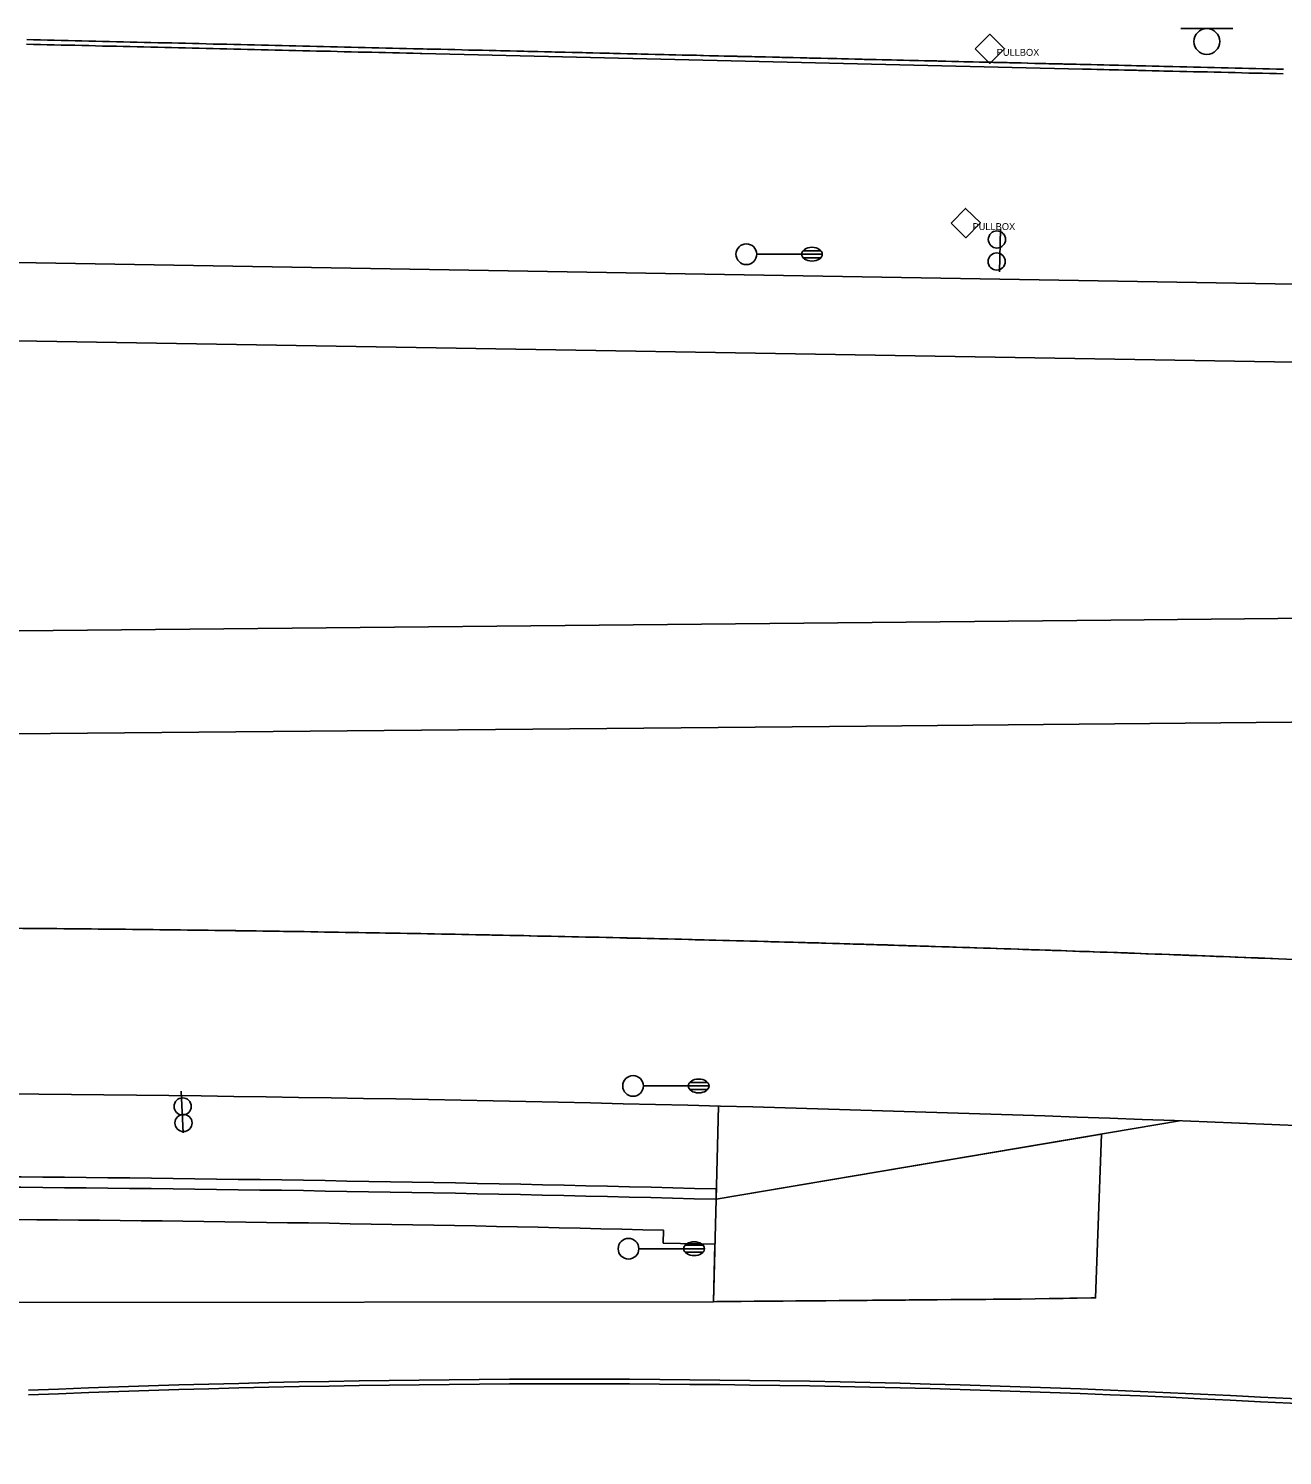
# Model space of a CAD drawing. Extents: x 2145380 to 2157287, y 139568 to 149130.
# Drawn here: x 2148110.3 to 2148291.9, y 142955.4 to 143162 of the extents above; entities that cross this region are included whole.
import ezdxf

# ---------------------------------------------------------------- set-up
doc = ezdxf.new("R2010")
doc.units = 0
for name, color, linetype in [('Default', 7, 'Continuous'), ('PR_PREVIOUSLY CONSTRUCTED', 7, 'Continuous'), ('TOPO_Asphalt', 7, 'Continuous'), ('TOPO_Curb Back', 7, 'Continuous'), ('TOPO_Light Pole', 7, 'Continuous'), ('TOPO_Misc', 7, 'Continuous'), ('TOPO_Power Pullbox', 7, 'Continuous'), ('TOPO_Sign', 7, 'Continuous')]:
    doc.layers.add(name, color=color, linetype=linetype)

# ---------------------------------------------------------------- blocks, each defined once
blk = doc.blocks.new('POST')
at = {"layer": 'TOPO_Misc'}
for start, end in [(90, 180), (180, 270), (360, 90), (270, 0)]:
    blk.add_arc((-0.01, 0.03), 3.16, start, end, dxfattribs=at)
blk = doc.blocks.new('LP')
at = {"layer": 'TOPO_Light Pole'}
blk.add_line((3.81, 0), (20.32, 0), dxfattribs=at)
for points in [[(20.32, 0), (27.94, 0)], [(20.32, 0), (23.5, 0)], [(20.83, 1.27), (27.43, 1.27)], [(20.83, 1.27), (23.5, 1.27)], [(23.71, 1.27), (27.43, 1.27)], [(23.71, 0), (27.94, 0)], [(20.83, -1.27), (27.43, -1.27)], [(20.83, -1.27), (23.5, -1.27)], [(23.71, -1.27), (27.43, -1.27)]]:
    blk.add_lwpolyline(points, dxfattribs=at)
blk.add_circle((0, 0), 3.81, dxfattribs=at)
blk.add_ellipse((24.13, 0), major_axis=(3.81, 0), ratio=0.666667, dxfattribs=at)
blk = doc.blocks.new('pulbox')
at = {"layer": 'Default'}
blk.add_lwpolyline([(-5.38, -0.01), (-0.02, 5.42), (5.4, 0.06), (0.05, -5.36), (-5.38, -0.01)], dxfattribs=at)
blk.add_text('PULLBOX', height=2.54, dxfattribs=at).set_placement((2.54, -2.54))

msp = doc.modelspace()

# ---------------------------------------------------------------- linework, layer by layer
at = {"layer": 'PR_PREVIOUSLY CONSTRUCTED'}
for p in [(2148210.23, 143005.99), (2148209.92, 142993.99)]:
    msp.add_line(p, (2148209.88, 142992.49), dxfattribs=at)
for points in [[(2148110.06, 143159.74), (2148111.06, 143159.72), (2148112.06, 143159.7), (2148113.06, 143159.67), (2148114.06, 143159.65), (2148115.06, 143159.62), (2148116.06, 143159.6), (2148117.06, 143159.58), (2148118.06, 143159.55), (2148119.06, 143159.53), (2148120.06, 143159.51), (2148121.06, 143159.48), (2148122.06, 143159.46), (2148123.06, 143159.44), (2148124.06, 143159.41), (2148125.06, 143159.39), (2148126.06, 143159.37), (2148127.06, 143159.34), (2148128.06, 143159.32), (2148129.06, 143159.3), (2148130.06, 143159.27), (2148131.06, 143159.25), (2148132.06, 143159.22), (2148133.06, 143159.2), (2148134.06, 143159.18), (2148135.06, 143159.15), (2148136.06, 143159.13), (2148137.06, 143159.11), (2148138.06, 143159.08), (2148139.06, 143159.06), (2148140.06, 143159.04), (2148141.06, 143159.01), (2148142.06, 143158.99), (2148143.05, 143158.97), (2148144.05, 143158.94), (2148145.05, 143158.92), (2148146.05, 143158.89), (2148147.05, 143158.87), (2148148.05, 143158.85), (2148149.05, 143158.82), (2148150.05, 143158.8), (2148151.05, 143158.78), (2148152.05, 143158.75), (2148153.05, 143158.73), (2148154.05, 143158.71), (2148155.05, 143158.68), (2148156.05, 143158.66), (2148157.05, 143158.64), (2148158.05, 143158.61), (2148159.05, 143158.59), (2148160.05, 143158.57), (2148161.05, 143158.54), (2148162.05, 143158.52), (2148163.05, 143158.49), (2148164.05, 143158.47), (2148165.05, 143158.45), (2148166.05, 143158.42), (2148167.05, 143158.4), (2148167.31, 143158.39), (2148262.94, 143156.14)], [(2148110.08, 143160.41), (2148111.08, 143160.39), (2148112.08, 143160.36), (2148113.08, 143160.34), (2148114.08, 143160.32), (2148115.08, 143160.29), (2148116.08, 143160.27), (2148117.08, 143160.24), (2148118.08, 143160.22), (2148119.08, 143160.2), (2148120.08, 143160.17), (2148121.08, 143160.15), (2148122.08, 143160.13), (2148123.08, 143160.1), (2148124.08, 143160.08), (2148125.08, 143160.06), (2148126.08, 143160.03), (2148127.07, 143160.01), (2148128.07, 143159.99), (2148129.07, 143159.96), (2148130.07, 143159.94), (2148131.07, 143159.92), (2148132.07, 143159.89), (2148133.07, 143159.87), (2148134.07, 143159.85), (2148135.07, 143159.82), (2148136.07, 143159.8), (2148137.07, 143159.77), (2148138.07, 143159.75), (2148139.07, 143159.73), (2148140.07, 143159.7), (2148141.07, 143159.68), (2148142.07, 143159.66), (2148143.07, 143159.63), (2148144.07, 143159.61), (2148145.07, 143159.59), (2148146.07, 143159.56), (2148147.07, 143159.54), (2148148.07, 143159.52), (2148149.07, 143159.49), (2148150.07, 143159.47), (2148151.07, 143159.44), (2148152.07, 143159.42), (2148153.07, 143159.4), (2148154.07, 143159.37), (2148155.07, 143159.35), (2148156.07, 143159.33), (2148157.07, 143159.3), (2148158.07, 143159.28), (2148159.07, 143159.26), (2148160.07, 143159.23), (2148161.07, 143159.21), (2148162.07, 143159.19), (2148163.06, 143159.16), (2148164.06, 143159.14), (2148165.06, 143159.11), (2148166.06, 143159.09), (2148167.06, 143159.07), (2148167.47, 143159.06), (2148167.49, 143159.06), (2148168.06, 143159.04), (2148169.06, 143159.02), (2148170.06, 143159), (2148171.06, 143158.97), (2148172.06, 143158.95), (2148173.06, 143158.93), (2148174.06, 143158.9), (2148175.06, 143158.88), (2148176.06, 143158.86), (2148177.06, 143158.83), (2148177.38, 143158.82), (2148178.06, 143158.81), (2148178.69, 143158.79), (2148179.06, 143158.79), (2148180.01, 143158.76), (2148180.06, 143158.76), (2148181.06, 143158.74), (2148181.32, 143158.73), (2148182.06, 143158.71), (2148182.64, 143158.7), (2148183.06, 143158.69), (2148183.95, 143158.67), (2148184.06, 143158.67), (2148185.06, 143158.64), (2148185.27, 143158.64), (2148186.06, 143158.62), (2148186.58, 143158.61), (2148187.06, 143158.6), (2148187.9, 143158.58), (2148188.06, 143158.57), (2148189.06, 143158.55), (2148189.22, 143158.55), (2148190.06, 143158.53), (2148190.53, 143158.52), (2148191.06, 143158.5), (2148191.85, 143158.48), (2148192.06, 143158.48), (2148193.06, 143158.46), (2148193.16, 143158.45), (2148194.06, 143158.43), (2148194.48, 143158.42), (2148195.06, 143158.41), (2148195.79, 143158.39), (2148196.06, 143158.38), (2148197.06, 143158.36), (2148197.11, 143158.36), (2148197.97, 143158.34), (2148197.98, 143158.34), (2148198.06, 143158.34), (2148198.42, 143158.33), (2148199.05, 143158.31), (2148199.74, 143158.3), (2148200.05, 143158.29), (2148201.05, 143158.27), (2148202.05, 143158.24), (2148202.37, 143158.24), (2148203.05, 143158.22), (2148203.69, 143158.2), (2148204.05, 143158.2), (2148205, 143158.17), (2148205.05, 143158.17), (2148206.05, 143158.15), (2148206.32, 143158.14), (2148207.05, 143158.13), (2148207.63, 143158.11), (2148208.05, 143158.1), (2148208.95, 143158.08), (2148209.05, 143158.08), (2148210.05, 143158.05), (2148210.26, 143158.05), (2148211.05, 143158.03), (2148211.58, 143158.02), (2148212.05, 143158.01), (2148212.89, 143157.99), (2148213.05, 143157.98), (2148214.05, 143157.96), (2148214.21, 143157.96), (2148215.05, 143157.94), (2148215.52, 143157.93), (2148216.05, 143157.91), (2148216.84, 143157.89), (2148217.05, 143157.89), (2148218.05, 143157.87), (2148218.15, 143157.86), (2148219.05, 143157.84), (2148219.47, 143157.83), (2148220.05, 143157.82), (2148220.79, 143157.8), (2148221.05, 143157.8), (2148222.05, 143157.77), (2148222.1, 143157.77), (2148223.05, 143157.75), (2148223.42, 143157.74), (2148224.05, 143157.72), (2148224.73, 143157.71), (2148225.05, 143157.7), (2148226.05, 143157.68), (2148227.05, 143157.65), (2148227.36, 143157.65), (2148228.05, 143157.63), (2148228.68, 143157.62), (2148229.05, 143157.61), (2148229.99, 143157.58), (2148230.05, 143157.58), (2148231.05, 143157.56), (2148231.31, 143157.55), (2148232.05, 143157.54), (2148232.62, 143157.52), (2148233.05, 143157.51), (2148233.94, 143157.49), (2148234.05, 143157.49), (2148235.05, 143157.47), (2148235.26, 143157.46), (2148236.04, 143157.44), (2148236.57, 143157.43), (2148237.04, 143157.42), (2148237.89, 143157.4), (2148238.04, 143157.4), (2148239.04, 143157.37), (2148239.2, 143157.37), (2148240.04, 143157.35), (2148240.52, 143157.34), (2148241.04, 143157.32), (2148241.83, 143157.31), (2148242.04, 143157.3), (2148243.04, 143157.28), (2148243.15, 143157.28), (2148244.04, 143157.25), (2148244.46, 143157.24), (2148244.68, 143157.24), (2148245.04, 143157.23), (2148245.78, 143157.21), (2148246.04, 143157.21), (2148247.04, 143157.18), (2148247.1, 143157.18), (2148248.04, 143157.16), (2148248.41, 143157.15), (2148249.04, 143157.14), (2148249.73, 143157.12), (2148250.03, 143157.11), (2148250.04, 143157.11), (2148251.04, 143157.09), (2148252.04, 143157.07), (2148252.36, 143157.06), (2148253.04, 143157.04), (2148253.67, 143157.03), (2148254.04, 143157.02), (2148254.99, 143157), (2148255.04, 143156.99), (2148256.04, 143156.97), (2148256.3, 143156.97), (2148257.04, 143156.95), (2148257.62, 143156.93), (2148258.04, 143156.92), (2148258.93, 143156.9), (2148259.04, 143156.9), (2148260.04, 143156.88), (2148260.25, 143156.87), (2148261.04, 143156.85), (2148261.56, 143156.84), (2148262.04, 143156.83), (2148262.61, 143156.82), (2148262.61, 143156.82), (2148262.88, 143156.81), (2148263.04, 143156.81), (2148264.04, 143156.78), (2148264.19, 143156.78), (2148265.04, 143156.76), (2148265.51, 143156.75), (2148266.04, 143156.74), (2148266.83, 143156.72), (2148267.04, 143156.71), (2148268.04, 143156.69), (2148268.14, 143156.69), (2148269.04, 143156.67), (2148269.46, 143156.66), (2148270.04, 143156.64), (2148270.77, 143156.62), (2148271.04, 143156.62), (2148272.03, 143156.6), (2148272.09, 143156.59), (2148273.03, 143156.57), (2148273.4, 143156.56), (2148274.03, 143156.55), (2148274.72, 143156.53), (2148275.03, 143156.52), (2148276.03, 143156.5), (2148277.03, 143156.48), (2148278.03, 143156.45), (2148279.03, 143156.43), (2148280.03, 143156.41), (2148281.03, 143156.38), (2148282.03, 143156.36), (2148283.03, 143156.34), (2148284.03, 143156.31), (2148285.03, 143156.29), (2148286.03, 143156.27), (2148287.03, 143156.24), (2148288.03, 143156.22), (2148289.03, 143156.19), (2148290.03, 143156.17), (2148291.03, 143156.15), (2148292.03, 143156.12)], [(2148262.94, 143156.14), (2148264.02, 143156.12), (2148264.18, 143156.11), (2148265.02, 143156.09), (2148265.49, 143156.08), (2148266.02, 143156.07), (2148266.81, 143156.05), (2148267.02, 143156.05), (2148268.02, 143156.02), (2148268.13, 143156.02), (2148269.02, 143156), (2148269.44, 143155.99), (2148270.02, 143155.97), (2148270.76, 143155.96), (2148271.02, 143155.95), (2148272.02, 143155.93), (2148272.07, 143155.93), (2148273.02, 143155.9), (2148273.39, 143155.89), (2148274.02, 143155.88), (2148274.7, 143155.86), (2148275.02, 143155.86), (2148276.02, 143155.83), (2148277.02, 143155.81), (2148278.02, 143155.79), (2148279.02, 143155.76), (2148280.02, 143155.74), (2148281.02, 143155.72), (2148282.02, 143155.69), (2148283.02, 143155.67), (2148284.02, 143155.64), (2148285.02, 143155.62), (2148286.02, 143155.6), (2148287.01, 143155.57), (2148288.01, 143155.55), (2148289.01, 143155.53), (2148290.01, 143155.5), (2148291.01, 143155.48), (2148292.01, 143155.46)], [(2148109.5, 143031.72), (2148110.49, 143031.71), (2148111.48, 143031.7), (2148112.48, 143031.7), (2148113.47, 143031.69), (2148114.46, 143031.68), (2148115.46, 143031.67), (2148115.91, 143031.66), (2148116.45, 143031.66), (2148117.45, 143031.65), (2148118.44, 143031.64), (2148119.44, 143031.63), (2148120.43, 143031.62), (2148121.42, 143031.61), (2148122.42, 143031.6), (2148123.41, 143031.59), (2148124.4, 143031.58), (2148125.4, 143031.57), (2148126.39, 143031.56), (2148127.38, 143031.55), (2148128.38, 143031.53), (2148129.37, 143031.52), (2148130.37, 143031.51), (2148131.29, 143031.5), (2148131.36, 143031.5), (2148132.35, 143031.49), (2148133.35, 143031.47), (2148134.34, 143031.46), (2148135.34, 143031.45), (2148136.33, 143031.44), (2148137.32, 143031.42), (2148138.32, 143031.41), (2148139.31, 143031.4), (2148140.3, 143031.38), (2148141.3, 143031.37), (2148142.29, 143031.35), (2148143.29, 143031.34), (2148144.28, 143031.33), (2148145.27, 143031.31), (2148146.27, 143031.3), (2148146.67, 143031.29), (2148147.26, 143031.28), (2148148.25, 143031.27), (2148149.25, 143031.25), (2148150.24, 143031.24), (2148151.24, 143031.22), (2148152.23, 143031.21), (2148153.22, 143031.19), (2148154.22, 143031.17), (2148155.21, 143031.16), (2148156.21, 143031.14), (2148157.2, 143031.13), (2148158.19, 143031.11), (2148159.19, 143031.09), (2148160.18, 143031.07), (2148161.17, 143031.06), (2148162.04, 143031.04), (2148162.17, 143031.04), (2148163.16, 143031.02), (2148164.15, 143031.01), (2148165.15, 143030.99), (2148166.14, 143030.97), (2148167.14, 143030.95), (2148168.13, 143030.93), (2148169.12, 143030.91), (2148170.12, 143030.9), (2148171.11, 143030.88), (2148172.1, 143030.86), (2148173.1, 143030.84), (2148174.09, 143030.82), (2148175.09, 143030.8), (2148176.08, 143030.78), (2148177.07, 143030.76), (2148177.42, 143030.75), (2148178.07, 143030.74), (2148179.06, 143030.72), (2148180.05, 143030.7), (2148181.05, 143030.68), (2148182.04, 143030.66), (2148183.03, 143030.64), (2148184.03, 143030.61), (2148185.02, 143030.59), (2148186.02, 143030.57), (2148187.01, 143030.55), (2148188, 143030.53), (2148189, 143030.51), (2148189.99, 143030.48), (2148190.98, 143030.46), (2148191.98, 143030.44), (2148192.79, 143030.42), (2148192.97, 143030.42), (2148193.97, 143030.39), (2148194.96, 143030.37), (2148195.95, 143030.35), (2148196.95, 143030.32), (2148197.94, 143030.3), (2148198.93, 143030.28), (2148199.93, 143030.25), (2148200.92, 143030.23), (2148201.91, 143030.2), (2148202.91, 143030.18), (2148203.9, 143030.15), (2148204.9, 143030.13), (2148205.89, 143030.11), (2148206.88, 143030.08), (2148207.88, 143030.05), (2148208.17, 143030.05), (2148208.87, 143030.03), (2148209.86, 143030), (2148210.86, 143029.98), (2148211.85, 143029.95), (2148212.84, 143029.93), (2148212.9, 143029.92), (2148213.84, 143029.9), (2148214.83, 143029.87), (2148214.94, 143029.87), (2148215.82, 143029.85), (2148216.82, 143029.82), (2148216.98, 143029.82), (2148217.81, 143029.79), (2148218.8, 143029.77), (2148219.02, 143029.76), (2148219.8, 143029.74), (2148220.79, 143029.71), (2148221.06, 143029.7), (2148221.78, 143029.68), (2148222.78, 143029.65), (2148223.11, 143029.64), (2148223.54, 143029.63), (2148223.77, 143029.63), (2148224.77, 143029.6), (2148225.15, 143029.59), (2148225.76, 143029.57), (2148226.75, 143029.54), (2148227.19, 143029.53), (2148227.75, 143029.51), (2148228.74, 143029.48), (2148229.23, 143029.47), (2148229.73, 143029.45), (2148230.73, 143029.42), (2148231.27, 143029.41), (2148231.72, 143029.39), (2148232.71, 143029.37), (2148233.31, 143029.35), (2148233.71, 143029.34), (2148234.7, 143029.31), (2148235.35, 143029.29), (2148235.69, 143029.28), (2148236.69, 143029.24), (2148237.4, 143029.22), (2148237.68, 143029.21), (2148238.67, 143029.18), (2148238.92, 143029.18), (2148239.44, 143029.16), (2148239.67, 143029.15), (2148240.66, 143029.12), (2148241.48, 143029.1), (2148241.65, 143029.09), (2148242.65, 143029.06), (2148243.52, 143029.03), (2148243.64, 143029.03), (2148244.63, 143029), (2148245.56, 143028.97), (2148245.63, 143028.96), (2148246.62, 143028.93), (2148247.6, 143028.9), (2148247.62, 143028.9), (2148248.61, 143028.87), (2148249.6, 143028.83), (2148249.64, 143028.83), (2148250.6, 143028.8), (2148251.59, 143028.77), (2148251.68, 143028.77), (2148252.58, 143028.74), (2148253.57, 143028.7), (2148253.72, 143028.7), (2148254.29, 143028.68), (2148254.57, 143028.67), (2148255.56, 143028.63), (2148255.77, 143028.63), (2148256.55, 143028.6), (2148257.55, 143028.57), (2148257.81, 143028.56), (2148258.54, 143028.53), (2148259.53, 143028.5), (2148259.85, 143028.49), (2148260.53, 143028.46), (2148261.52, 143028.43), (2148261.89, 143028.42), (2148262.51, 143028.39), (2148263.51, 143028.36), (2148263.93, 143028.35), (2148264.5, 143028.32), (2148265.49, 143028.29), (2148265.97, 143028.27), (2148266.49, 143028.25), (2148267.48, 143028.22), (2148268.01, 143028.2), (2148268.47, 143028.18), (2148269.47, 143028.15), (2148269.66, 143028.14), (2148270.05, 143028.12), (2148270.46, 143028.11), (2148271.45, 143028.07), (2148272.09, 143028.05), (2148272.45, 143028.04), (2148273.44, 143028), (2148274.13, 143027.97), (2148274.43, 143027.96), (2148275.43, 143027.93), (2148276.17, 143027.9), (2148276.42, 143027.89), (2148277.41, 143027.85), (2148278.22, 143027.82), (2148278.41, 143027.81), (2148279.4, 143027.78), (2148280.26, 143027.74), (2148280.39, 143027.74), (2148281.39, 143027.7), (2148282.3, 143027.66), (2148282.38, 143027.66), (2148283.37, 143027.62), (2148284.34, 143027.58), (2148284.37, 143027.58), (2148285.02, 143027.56), (2148285.36, 143027.55), (2148286.35, 143027.51), (2148286.38, 143027.51), (2148287.34, 143027.47), (2148288.34, 143027.43), (2148288.42, 143027.42), (2148289.33, 143027.39), (2148290.32, 143027.35), (2148290.46, 143027.34), (2148291.32, 143027.31), (2148292.31, 143027.27)], [(2148209.88, 142992.49), (2148277, 143003.85)], [(2148008.66, 142989.5), (2147788.62, 142987.41), (2147708.66, 142988.25), (2147708.93, 142959.42), (2148055.74, 142975.32), (2148108.42, 142977.52), (2148209.49, 142977.66), (2148209.49, 142977.66), (2148209.71, 142986)], [(2148209.71, 142986), (2148202.25, 142986.15), (2148202.29, 142988.02)]]:
    msp.add_lwpolyline(points, dxfattribs=at)
msp.add_lwpolyline([(2148209.49, 142977.66), (2148210.01, 142977.67), (2148210, 142977.67), (2148210, 142977.67), (2148211.51, 142977.68), (2148211.52, 142977.68), (2148211.52, 142977.68), (2148213.41, 142977.7), (2148213.41, 142977.7), (2148213.42, 142977.7), (2148213.54, 142977.7), (2148213.54, 142977.7), (2148213.54, 142977.7), (2148215.41, 142977.72), (2148215.41, 142977.72), (2148215.42, 142977.72), (2148215.57, 142977.72), (2148215.56, 142977.72), (2148215.56, 142977.72), (2148217.59, 142977.73), (2148217.59, 142977.73), (2148217.6, 142977.73), (2148219.35, 142977.75), (2148219.35, 142977.75), (2148219.35, 142977.75), (2148219.62, 142977.75), (2148219.61, 142977.75), (2148219.62, 142977.75), (2148221.45, 142977.77), (2148221.64, 142977.77), (2148221.64, 142977.77), (2148221.65, 142977.77), (2148222.08, 142977.77), (2148222.07, 142977.77), (2148222.07, 142977.77), (2148223.67, 142977.79), (2148223.67, 142977.79), (2148225.69, 142977.8), (2148225.69, 142977.8), (2148225.7, 142977.8), (2148225.79, 142977.8), (2148225.78, 142977.8), (2148225.78, 142977.8), (2148225.79, 142977.8), (2148225.79, 142977.8), (2148227.71, 142977.82), (2148227.72, 142977.82), (2148229.2, 142977.83), (2148229.21, 142977.83), (2148229.74, 142977.84), (2148229.74, 142977.84), (2148231.36, 142977.85), (2148231.77, 142977.85), (2148231.77, 142977.85), (2148232.52, 142977.86), (2148232.51, 142977.86), (2148233.8, 142977.87), (2148233.79, 142977.87), (2148235.82, 142977.89), (2148235.83, 142977.89), (2148237.32, 142977.9), (2148237.33, 142977.9), (2148237.84, 142977.91), (2148237.84, 142977.91), (2148238.76, 142977.91), (2148238.76, 142977.91), (2148239.06, 142977.92), (2148239.06, 142977.92), (2148239.63, 142977.92), (2148239.63, 142977.92), (2148239.87, 142977.92), (2148239.87, 142977.92), (2148241.28, 142977.93), (2148241.9, 142977.94), (2148241.89, 142977.94), (2148243.92, 142977.96), (2148243.93, 142977.96), (2148245.95, 142977.98), (2148245.94, 142977.98), (2148247.97, 142977.99), (2148247.98, 142977.99), (2148248.92, 142978), (2148248.91, 142978), (2148250, 142978.01), (2148249.99, 142978.01), (2148251.2, 142978.02), (2148252.02, 142978.03), (2148252.03, 142978.03), (2148252.58, 142978.03), (2148252.58, 142978.03), (2148254.03, 142978.04), (2148254.04, 142978.04), (2148254.05, 142978.04), (2148256.07, 142978.07), (2148256.08, 142978.07), (2148258.1, 142978.11), (2148258.11, 142978.11), (2148258.78, 142978.12), (2148258.77, 142978.12), (2148260.13, 142978.14), (2148260.12, 142978.14), (2148261.12, 142978.15), (2148262.16, 142978.17), (2148262.15, 142978.17), (2148264.18, 142978.2), (2148264.19, 142978.2), (2148264.83, 142978.21), (2148265.68, 143001.93), (2148209.88, 142992.49)], close=True, dxfattribs=at)
for centre, radius, start, end in [((2148062.24, 137337.34), 5694.58, 87.50456, 90.54316), ((2148062.24, 137337.34), 5670.58, 87.50456, 90.54316), ((2148062.24, 137337.34), 5658.58, 88.50456, 90.54316), ((2148062.24, 137337.34), 5657.08, 88.50456, 90.54316), ((2148062.24, 137337.34), 5652.41, 88.58024, 90.54316), ((2148188.94, 141042.91), 1923.53, 84.04429, 92.3423), ((2148188.94, 141042.91), 1922.86, 84.04429, 92.3423)]:
    msp.add_arc(centre, radius, start, end, dxfattribs=at)
at = {"layer": 'TOPO_Asphalt'}
for p, q in [((2148326.9, 143124.43), (2147731.94, 143134.55)), ((2148343.89, 143112.85), (2147732.05, 143123.05))]:
    msp.add_line(p, q, dxfattribs=at)
for points in [[(2147832.97, 143072.35), (2147927.95, 143073.19), (2148079.29, 143074.53), (2148267.02, 143076.34), (2148475.01, 143078.41)], [(2148365.01, 143062.26), (2148231.65, 143061), (2148075.9, 143059.61), (2147932.72, 143058.25), (2147837.35, 143057.4)]]:
    msp.add_lwpolyline(points, dxfattribs=at)
at = {"layer": 'TOPO_Curb Back'}
for radius in [1923.53, 1922.86]:
    msp.add_arc((2148188.94, 141042.91), radius, 84.04429, 92.3423, dxfattribs=at)
at = {"layer": 'TOPO_Sign'}
for points in [[(2148277.19, 143162), (2148284.68, 143162.01)], [(2148280.94, 143162), (2148280.94, 143162)], [(2148279.07, 143160.13), (2148279.07, 143160.13)], [(2148282.81, 143160.13), (2148282.81, 143160.13)], [(2148280.94, 143158.27), (2148280.94, 143158.27)], [(2148251.07, 143132.98), (2148250.94, 143126.78)], [(2148132.72, 143002.13), (2148132.45, 143008.14)]]:
    msp.add_lwpolyline(points, dxfattribs=at)
for start, end in [(90, 180), (360, 90), (180, 270), (270, 0)]:
    msp.add_arc((2148280.94, 143160.13), 1.87, start, end, dxfattribs=at)

# ---------------------------------------------------------------- block references
at = {"layer": 'TOPO_Light Pole', "xscale": 0.39370000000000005, "yscale": 0.3937000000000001}
for p in [(2148214.27, 143129.33), (2148197.87, 143008.9), (2148197.21, 142985.33)]:
    msp.add_blockref('LP', p, dxfattribs=at)
at = {"layer": 'TOPO_Misc', "xscale": 0.39370000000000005, "yscale": 0.3937000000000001}
for p in [(2148250.55, 143131.46), (2148250.52, 143128.26), (2148132.66, 143005.92), (2148132.79, 143003.53)]:
    msp.add_blockref('POST', p, dxfattribs=at)
at = {"layer": 'TOPO_Power Pullbox', "xscale": 0.39370000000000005, "yscale": 0.3937000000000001}
for p in [(2148249.52, 143159.06), (2148246.02, 143133.83)]:
    msp.add_blockref('pulbox', p, dxfattribs=at)

doc.saveas('drawing.dxf')
